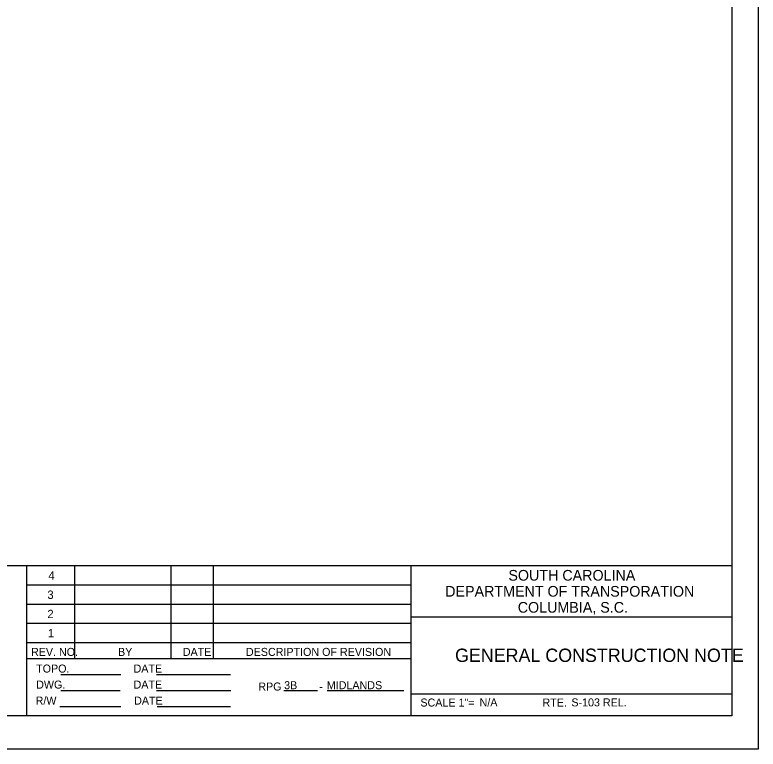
# Model space of a CAD drawing. Extents: x -796 to 2793, y -4650 to 4425.
# Drawn here: x 2221 to 2777, y -3500 to -2950 of the extents above; entities that cross this region are included whole.
import ezdxf

# ---------------------------------------------------------------- set-up
doc = ezdxf.new("R2010")
doc.units = 0
for name, color, linetype in [('RD_HC_CL', 7, 'Continuous'), ('RD_HC_Data', 7, 'Continuous'), ('RD_HC_Data_Tic', 7, 'Continuous')]:
    doc.layers.add(name, color=color, linetype=linetype)

msp = doc.modelspace()

# ---------------------------------------------------------------- linework, layer by layer
at = {"layer": 'RD_HC_CL'}
msp.add_lwpolyline([(981.4, -2400), (2777.4, -2400), (2777.4, -3500), (981.4, -3500)], close=True, dxfattribs=at)
at = {"layer": 'RD_HC_Data'}
for p, q in [((1995.01, -3362.55), (2757.6, -3362.55)), ((2229.59, -3475), (2229.59, -3362.55)), ((2229.59, -3362.55), (2229.59, -3362.55)), ((2265.59, -3432.24), (2265.59, -3362.55)), ((2337.59, -3432.24), (2337.59, -3362.55)), ((2369.41, -3432.1), (2369.41, -3362.5)), ((2517.59, -3475), (2517.59, -3362.55)), ((2229.59, -3376.9), (2517.59, -3376.9)), ((2229.59, -3391.3), (2517.59, -3391.3)), ((2517.59, -3400.9), (2757.6, -3400.9)), ((2229.59, -3405.7), (2517.59, -3405.7)), ((2229.59, -3420.1), (2517.59, -3420.1)), ((2229.59, -3432.1), (2517.59, -3432.1)), ((2255.03, -3444.1), (2299.91, -3444.1)), ((2326.79, -3444.1), (2382.08, -3444.1)), ((2255.03, -3456.1), (2299.52, -3456.1)), ((2326.79, -3456.1), (2382.51, -3456.1)), ((2422.11, -3456.1), (2447.32, -3456.1)), ((2454.51, -3456.1), (2512.02, -3456.1)), ((2517.59, -3458.5), (2757.6, -3458.5)), ((2254.21, -3468.1), (2299.91, -3468.1)), ((2327.17, -3468.1), (2382.08, -3468.1)), ((2760, -3500), (1000, -3500)), ((2760, -3500), (1000, -3500))]:
    msp.add_line(p, q, dxfattribs=at)
msp.add_lwpolyline([(1082.6, -2425), (2757.6, -2425), (2757.6, -3475), (1082.6, -3475)], close=True, dxfattribs=at)

# ---------------------------------------------------------------- texts
at = {"layer": 'RD_HC_Data_Tic'}
for s, height, p in [('4', 6.24, (2245.76, -3373.06)), ('SOUTH CAROLINA', 8, (2590.31, -3373.79)), ('DEPARTMENT OF TRANSPORATION', 8, (2542.97, -3385.79)), ('3', 6.24, (2244.99, -3387.46)), ('COLUMBIA, S.C.', 8, (2597.31, -3397.79)), ('2', 6.24, (2244.99, -3401.86)), ('1', 6.24, (2245.38, -3416.26)), ('REV. NO.', 6, (2232.71, -3430.18)), ('BY', 6, (2297.89, -3430.18)), ('DATE', 6, (2346.42, -3430.18)), ('DESCRIPTION OF REVISION', 6, (2393.7, -3430.18)), ('   GENERAL CONSTRUCTION NOTE   ', 10, (2539.2, -3434.7)), ('TOPO.', 6, (2236.55, -3442.66)), ('DATE', 6, (2309.51, -3442.66)), ('DWG.', 6, (2236.55, -3454.66)), ('DATE', 6, (2309.51, -3454.66)), ('RPG', 6, (2402.96, -3456.1)), ('3B    ', 6, (2422.31, -3455.12)), ('MIDLANDS   ', 6, (2454.29, -3455.12)), ('-', 6, (2448.7, -3456.1)), ('R/W', 6, (2236.16, -3466.66)), ('DATE', 6, (2309.94, -3466.66)), ('SCALE 1"=', 6, (2524.4, -3468.1)), ('N/A        ', 6, (2568.76, -3467.99)), ('RTE.', 6, (2615.84, -3468.1)), ('S-103 REL. ', 6, (2637.49, -3467.99))]:
    msp.add_text(s, height=height, dxfattribs=at).set_placement(p)

doc.saveas('drawing.dxf')
